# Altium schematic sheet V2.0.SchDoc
size A3; SheetNumber: 1; SheetTotal: 2
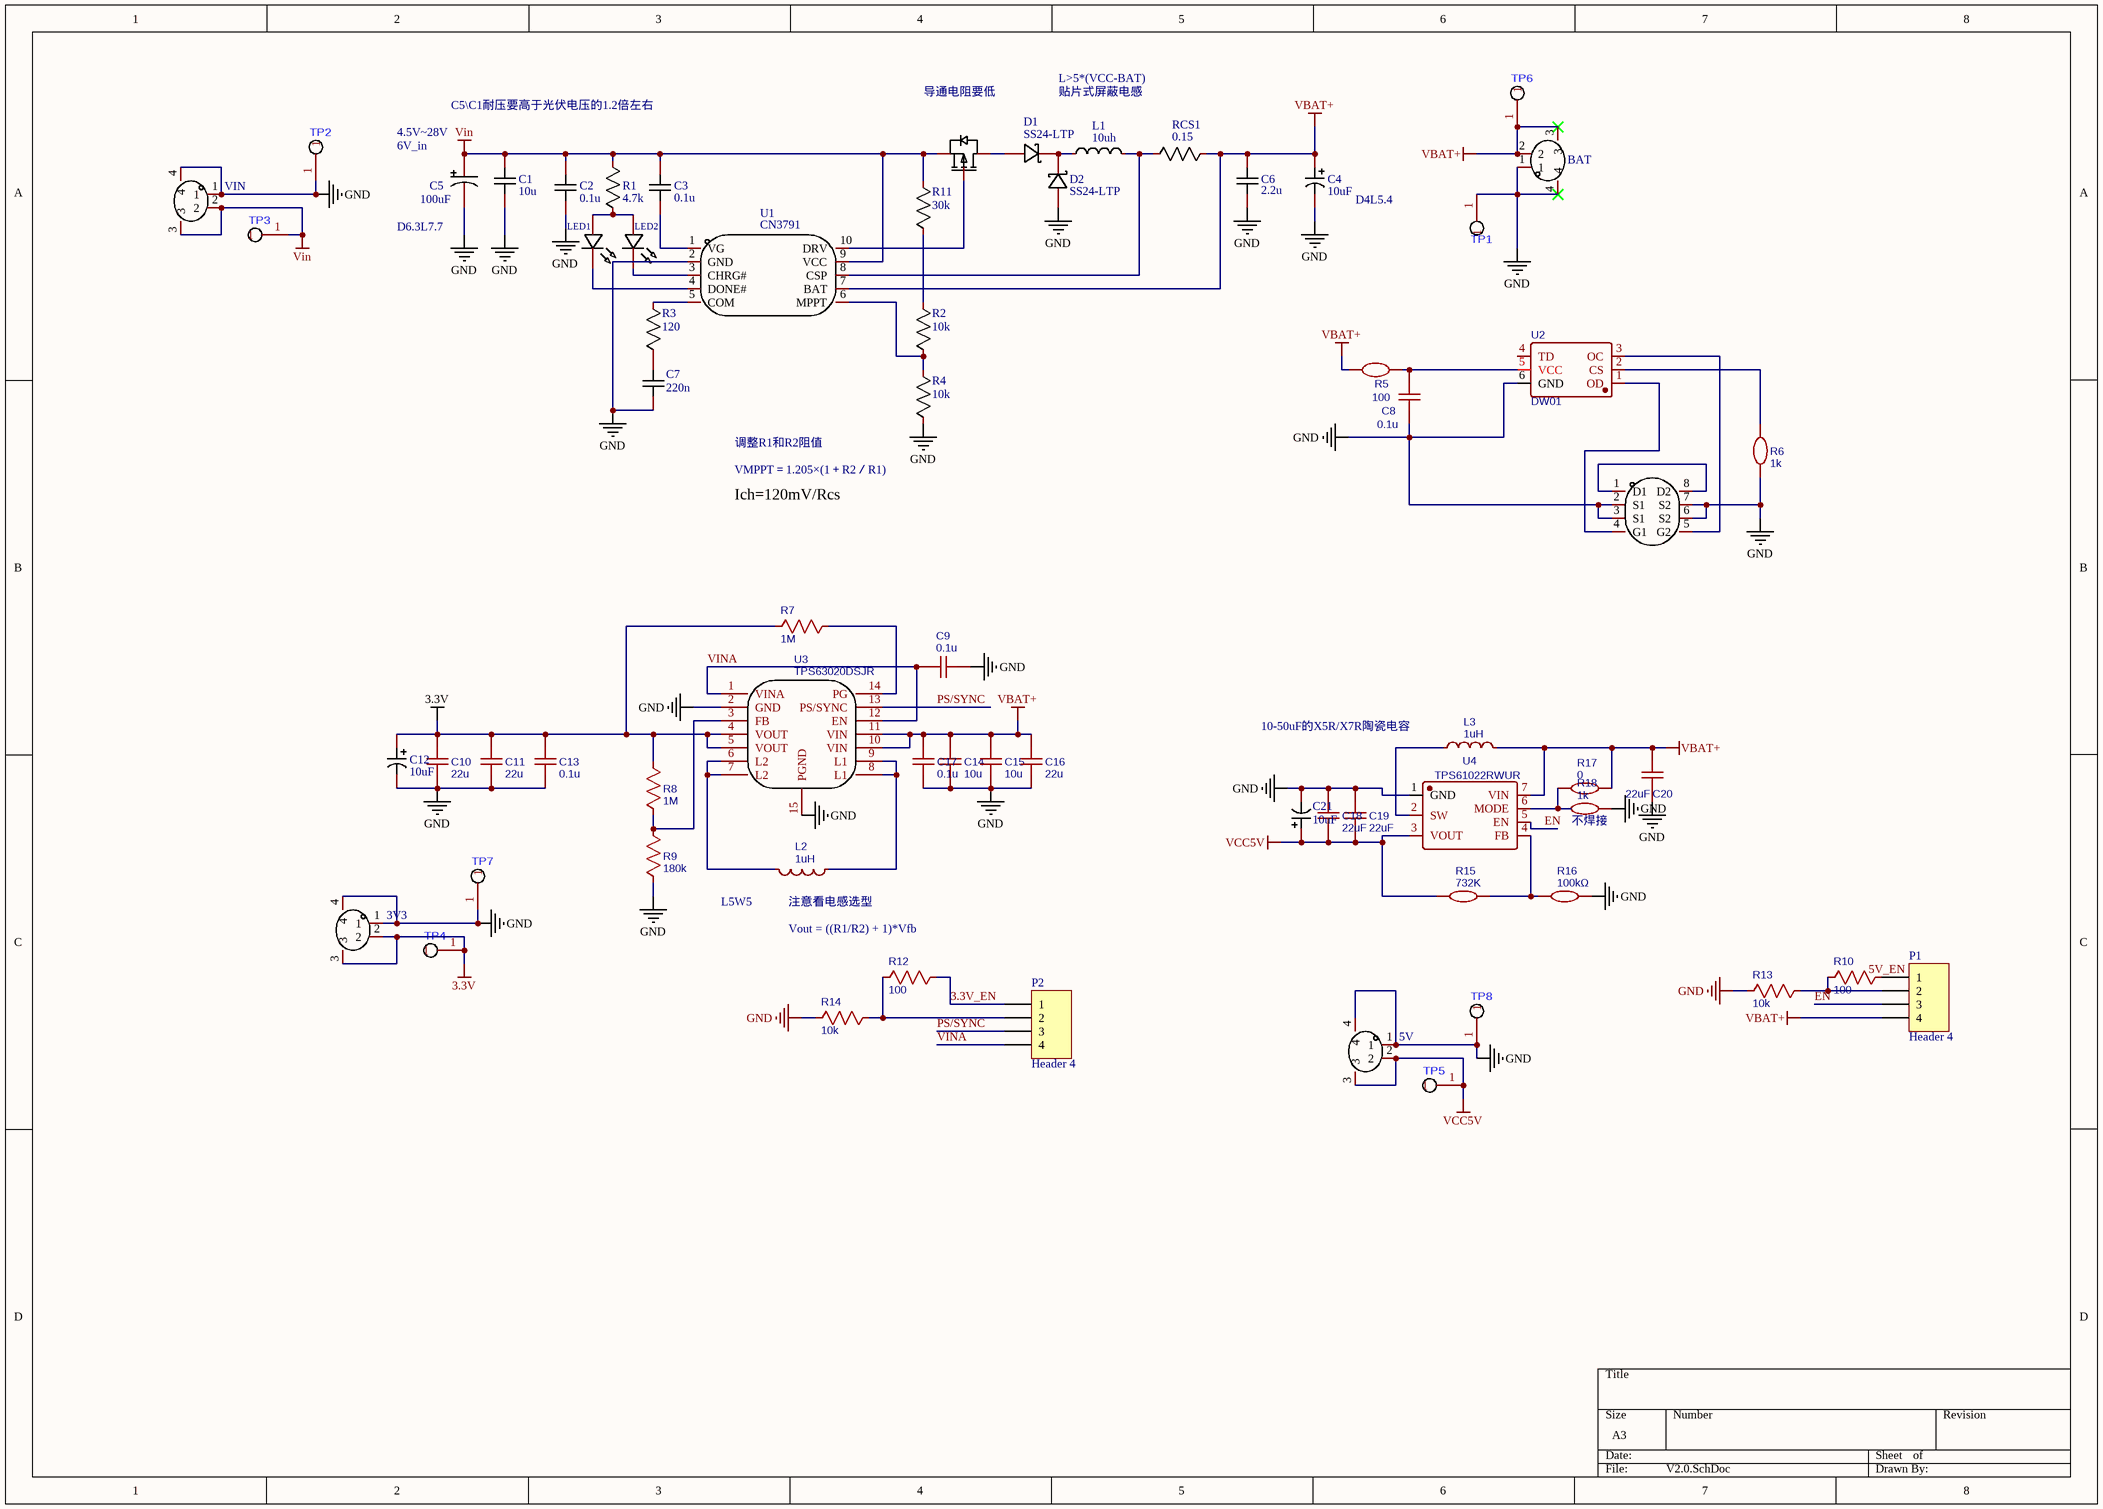
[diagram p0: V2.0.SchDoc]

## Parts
3V3  AFC12-S02DCC-00  [CONN-SMD_B2B-PH-SM4-TB-LF-SN]  (value not drawn)
5V  AFC12-S02DCC-00  [CONN-SMD_B2B-PH-SM4-TB-LF-SN]  (value not drawn)
BAT  AFC12-S02DCC-00  [CONN-SMD_B2B-PH-SM4-TB-LF-SN]  (value not drawn)
C1  10u  [C0805]
C2  0.1u  [C0805]
C3  0.1u  [C0805]
C4  10uF  [CAP-SMD_L7.3-W4.3-R-RD]
C5  Name: 100uF  [CAP-SMD_L7.3-W4.3]  (hidden comment: 220uF)
C6  2.2u  [C0805]
C7  220n  [C0805]
C8  0.1u  [C0805]
C9  0.1u  [C0805]
C10  22u  [C0805]
C11  22u  [C0805]
C12  10uF  [CAP-SMD_L7.3-W4.3-R-RD]
C13  0.1u  [C0805]
C14  10u  [C0805]
C15  10u  [C0805]
C16  22u  [C0805]
C17  0.1u  [C0805]
C18  22uF  [C0805]
C19  22uF  [C0805]
C20  22uF  [C0805]
C21  10uF  [CAP-SMD_L7.3-W4.3-R-RD]
D1  Name: SS24-LTP  [SMA(DO-214AC)SS24-LTP]  (hidden comment: SS34-A)
D2  Name: SS24-LTP  [SMA(DO-214AC)SS24-LTP]  (hidden comment: SS34-A)
L1  Name: 10uh  [IND-SMD_L11.5-W10.0_SMMS1040]  (hidden comment: 220uh)
L2  1uH  [IND-SMD_L7.1-W6.6]
L3  1uH  [IND-SMD_L7.1-W6.6]
LED1  LED-0603_R  [LED0805-R-RD]  (value not drawn)
LED2  LED-0603_R  [LED0805-R-RD]  (value not drawn)
P1  Header 4  [HDR-TH_4P-P2.00-V-M]
P2  Header 4  [HDR-TH_4P-P2.00-V-M]
Q1  AOD4185_C5371006  [(AOD4185)TO-252-2_L6.6-W6.1-P4.57-LS9.9-BR-CW]  (value not drawn)
R1  Name: 4.7k  [R0805 - duplicate]  (hidden comment: 1k)
R2  Name: 10k  [R0805 - duplicate]  (hidden comment: 1k)
R3  120  [R0805 - duplicate]
R4  Name: 10k  [R0805 - duplicate]  (hidden comment: 1k)
R5  100  [R0805 - duplicate]
R6  1k  [R0805 - duplicate]
R7  1M  [R0805 - duplicate]
R8  1M  [R0805 - duplicate]
R9  180k  [R0805 - duplicate]
R10  100  [R0805 - duplicate]
R11  Name: 30k  [R0805 - duplicate]  (hidden comment: 1k)
R12  100  [R0805 - duplicate]
R13  10k  [R0805 - duplicate]
R14  10k  [R0805 - duplicate]
R15  732K  [R0805 - duplicate]
R16  100kΩ  [R0805 - duplicate]
R17  0  [R0805 - duplicate]
R18  1k  [R0805 - duplicate]
RCS1  0.15  [R2512]
TP1  (no value)  [PCBComponent_1]
TP2  (no value)  [PCBComponent_1]
TP3  (no value)  [PCBComponent_1]
TP4  (no value)  [PCBComponent_1]
TP5  (no value)  [PCBComponent_1]
TP6  (no value)  [PCBComponent_1]
TP7  (no value)  [PCBComponent_1]
TP8  (no value)  [PCBComponent_1]
U1  CN3791  [SSOP-10_L4.9-W3.9-P1.00-LS6.0-BL]
U2  DW01  [SOT-23-6_L2.9-W1.6-P0.95-LS2.8-BL(DW01A)]
U3  TPS63020DSJR  [VSON-14_L4.0-W3.0-P0.50-BL-EP_TI_DSJ]
U4  TPS61022RWUR  [（TPS61022）VQFN-7_L2.0-W2.0-P0.55-TL_RWU]
U6  8205A_C5148694  [TSSOP-8_L4.4-W3.0-P0.65-LS6.4-BL]  (value not drawn)
VIN  AFC12-S02DCC-00  [CONN-SMD_B2B-PH-SM4-TB-LF-SN]  (value not drawn)

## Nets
3.3V: 3V3.2 3V3.3 C10.1 C11.1 C12.1 C13.1 R7.1 R8.2 TP4.1 U3.4(VOUT) U3.5(VOUT)
GND: 3V3.1 3V3.4 5V.1 5V.4 BAT.1 BAT.4 C1.1 C2.1 C4.2 C5.2 C6.1 C7.2 C8.1 C9.2 C10.2 C11.2 C12.2 C13.2 C14.1 C15.1 C16.2 C17.2 C18.2 C19.2 C20.1 C21.2 D2.2(A) R4.2 R6.2 R9.1 R13.1 R14.1 R16.2 R18.2 TP1.1 TP2.1 TP7.1 TP8.1 U1.2(GND) U2.6(GND) U3.2(GND) U3.15(PGND) U4.1(GND) U6.2(S1) U6.3(S1) U6.6(S2) U6.7(S2) VIN.1 VIN.4
VBAT+: BAT.2 BAT.3 C4.1 C6.2 C14.2 C15.2 C16.1 C17.1 C20.2 L3.2 P1.4 R5.2 R17.2 RCS1.2 TP6.1 U1.7(BAT) U3.10(VIN) U3.11(VIN) U4.7(VIN)
VCC5V: 5V.2 5V.3 C18.1 C19.1 C21.1 R15.1 TP5.1 U4.3(VOUT)
Vin: C1.2 C2.2 C3.2 C5.1 Q1.3(S) R1.2 R11.1 TP3.1 U1.9(VCC) VIN.2 VIN.3
3.3V_EN: P2.1 R12.2
EN: P1.3 U4.5(EN)
PS/SYNC: P2.3 U3.13(PS/SYNC)
VINA: C9.1 P2.4 U3.1(VINA) U3.12(EN)
NetC3_1: C3.1 U1.1(VG)
NetC7_1: C7.1 R3.2
NetC8_2: C8.2 R5.1 U2.5(VCC)
NetD1_1: D1.1(C) D2.1(C) L1.1
NetD1_2: D1.2(A) Q1.2(D)
NetL1_2: L1.2 RCS1.1 U1.8(CSP)
NetL2_1: L2.1 U3.8(L1) U3.9(L1)
NetL2_2: L2.2 U3.6(L2) U3.7(L2)
NetL3_1: L3.1 U4.2(SW)
NetLED1_1: LED1.1 LED2.1 R1.1
NetLED1_2: LED1.2 U1.4(DONE#)
NetLED2_2: LED2.2 U1.3(CHRG#)
NetP1_1: P1.1 R10.2
NetP1_2: P1.2 R10.1 R13.2
NetP2_2: P2.2 R12.1 R14.2
NetQ1_1: Q1.1(G) U1.10(DRV)
NetR2_1: R2.1 R11.2
NetR2_2: R2.2 R4.1 U1.6(MPPT)
NetR3_1: R3.1 U1.5(COM)
NetR6_1: R6.1 U2.2(CS)
NetR7_2: R7.2 U3.14(PG)
NetR8_1: R8.1 R9.2 U3.3(FB)
NetR15_2: R15.2 R16.1 U4.4(FB)
NetR17_1: R17.1 R18.1 U4.6(MODE)
NetU2_1: U2.1(OD) U6.4(G1)
NetU2_3: U2.3(OC) U6.5(G2)
NetU6_1: U6.1(D1) U6.8(D2)

Not connected (* = marked no-connect by the designer): U2 4(TD)

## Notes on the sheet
- C5\C1耐压要高于光伏电压的1.2倍左右
- 导通电阻要低
- 贴片式屏蔽电感
- L>5*(VCC-BAT)
- 4.5V|8V
- (near C5) 6V_in
- D6.3L7.7
- (near C4) D4L5.4
- 调整R1和R2阻值
- Ich=120mV/Rcs
- VMPPT＝1.205×(1＋R2／R1)
- 10-50uF的X5R/X7R陶瓷电容
- (near R18) 不焊接
- (near L2) L5W5
- (near L2) 注意看电感选型
- Vout = ((R1/R2) + 1)*Vfb
- Labels drawn without touching a wire or pin: 5V_EN

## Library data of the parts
3V3 5V BAT VIN = AFC12-S02DCC-00: Manufacturer: JUSHUO; Convert to PCB: yes; Origin Footprint: CONN-SMD_AFC12-S02DCC-00
C1 = 10u: Convert to PCB: yes; Origin Footprint: C1206
C2 C3 = 0.1u: Convert to PCB: yes; Origin Footprint: C0603
C4 C12 C21 = T494A106M020AT: Manufacturer: KEMET(基美); Convert to PCB: yes; Origin Footprint: CAP-SMD_L3.2-W1.6
C5 = VT1V221M-CRF10: Manufacturer: Vertical Technology; Convert to PCB: yes; Origin Footprint: CAP-SMD_BD8.0-L8.3-W8.3-LS9.5-FD
C6 = 2.2u: Convert to PCB: yes; Origin Footprint: C0603
C7 = 220n: Convert to PCB: yes; Origin Footprint: C0402_NEW
C8 C9 = 0.1u: nameAlias: Value(F); Contributor: LCEDA_Lib
C10 C11 C13 C16 C17 = 22u: nameAlias: Value(F); Contributor: LCEDA_Lib
C14 C15 = 10u: nameAlias: Value(F); Contributor: LCEDA_Lib
C18-C20 = 22uF: Manufacturer: SAMSUNG(三星); Manufacturer Part: CL21A226MAQNNNE; nameAlias: Capacitance
D1 D2 = SS34-A: Manufacturer: Formosa Microsemi; Convert to PCB: yes; Origin Footprint: SMA_L4.3-W2.6-LS5.2-RD
L1 = 220uh: Convert to PCB: yes; Origin Footprint: IND-SMD_L12.0-W12.0_CDRH127NP
L2 = 10uH: Manufacturer: TDK; Manufacturer Part: VLS5045EX-100M-CA; nameAlias: Inductance; Contributor: LCSC
L3 = 1uH: Manufacturer: Sunlord(顺络); Manufacturer Part: MWSA0603S-1R0MT; nameAlias: Inductance; Contributor: LCSC
LED1 = 19-217/R6C-AL1M2VY/3T: Manufacturer: EVERLIGHT(台湾亿光); Convert to PCB: yes; Origin Footprint: LED0603_RED
LED2 = 19-217/R6C-AL1M2VY/3T: Manufacturer: EVERLIGHT(台湾亿光); Convert to PCB: yes; Origin Footprint: LED0603_GREEN
P1 P2 = Header 4: Header, 4-Pin
Q1 = AOD4185_C5371006: Manufacturer: TECH PUBLIC(台舟); Add into BOM: yes
R1 = 1k: Convert to PCB: yes; Origin Footprint: R0603
R2 R4 R11 = 1k: Convert to PCB: yes; Origin Footprint: C0402_NEW
R3 = 120: Convert to PCB: yes; Origin Footprint: C0402_NEW
R5 = 100: nameAlias: Value(Ω); Contributor: LCEDA_Lib
R6 = 1k: nameAlias: Value(Ω); Contributor: LCEDA_Lib
R7 R8 R10 R12-R14 = 1M: nameAlias: Value(Ω); Contributor: LCEDA_Lib
R9 = 180k: nameAlias: Value(Ω); Contributor: LCEDA_Lib
R15 = 732K: Manufacturer: YAGEO(国巨); Manufacturer Part: AC0603FR-07732KL; nameAlias: Resistance (Ohms); Contributor: LCSC; Resistance: 732kΩ
R16-R18 = 100kΩ: Manufacturer: FH(风华); Manufacturer Part: RS-03K1003FT; Resistance (Ohms): 100K; nameAlias: Resistance; Contributor: LCSC
RCS1 = 0.15: Convert to PCB: yes
TP1-TP8 = 测试焊盘
U1 = CN3791: Manufacturer: ShangHai Consonance Elec; Convert to PCB: yes
U2 = DW01: Manufacturer: Hottech; Contributor: LCSC; SMT Type: Extend
U3 = TPS63020DSJR: Manufacturer: TI; SMT Type: Extend
U4 = TPS61022RWUR: Manufacturer: TI(德州仪器); Contributor: LCSC
U6 = 8205A_C5148694: Manufacturer: HXY MOSFET(华轩阳电子); Name: 8205A; Add into BOM: yes; Gate Threshold Voltage (Vgs(th)@Id): 1.2V@250uA; Drain Source Voltage (Vdss): 20V; Continuous Drain Current (Id): 6A; Power Dissipation (Pd): 1.5W; Drain Source On Resistance (RDS(on)@Vgs,Id): 23mΩ@4.5V; Input Capacitance (Ciss@Vds): 600pF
